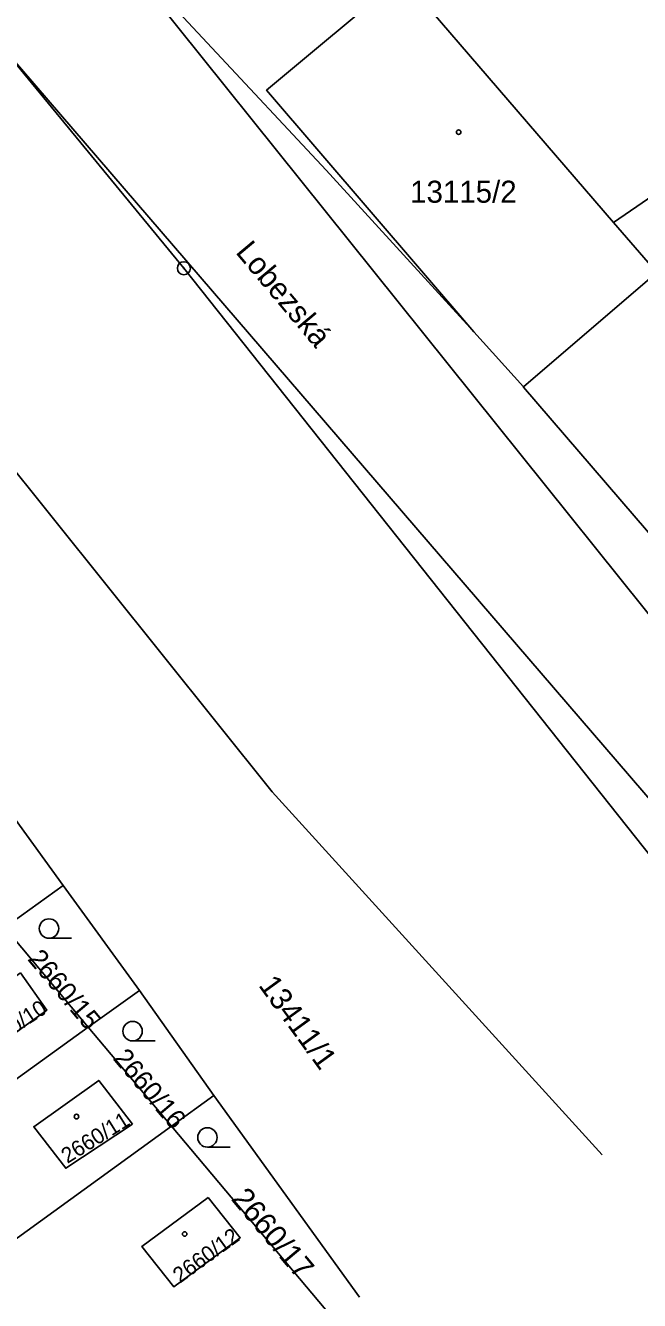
# Model space of a CAD drawing. Extents: x -821458 to -820266, y -1071458 to -1069826.
# Drawn here: x -820545.4 to -820498, y -1071392.4 to -1071294.1 of the extents above; entities that cross this region are included whole.
import ezdxf

# ---------------------------------------------------------------- set-up
doc = ezdxf.new("R2010")
doc.units = 0
for name, color, linetype in [('Vrstva 1', 7, 'Continuous'), ('Vrstva 2', 7, 'Continuous'), ('Vrstva 3', 7, 'Continuous'), ('Vrstva 4', 7, 'Continuous'), ('Vrstva 5', 7, 'Continuous'), ('Vrstva 6', 7, 'Continuous'), ('Vrstva 7', 7, 'Continuous'), ('Vrstva 8', 7, 'Continuous')]:
    doc.layers.add(name, color=color, linetype=linetype)

msp = doc.modelspace()

# ---------------------------------------------------------------- linework, layer by layer
at = {"layer": 'Vrstva 1'}
for p, q in [((-820506.98, -1071321.94), (-820510.8, -1071317.69)), ((-820542.47, -1071360.42), (-820554.5, -1071343.84)), ((-820546.99, -1071363.66), (-820542.47, -1071360.42)), ((-820542.47, -1071360.42), (-820536.6, -1071368.5)), ((-820540.54, -1071371.34), (-820546.99, -1071363.66)), ((-820540.54, -1071371.34), (-820536.6, -1071368.5)), ((-820536.6, -1071368.5), (-820530.86, -1071376.6)), ((-820557.71, -1071383.7), (-820540.54, -1071371.34)), ((-820534.12, -1071378.97), (-820540.54, -1071371.34)), ((-820534.12, -1071378.97), (-820530.86, -1071376.6)), ((-820534.12, -1071378.97), (-820551.8, -1071391.81))]:
    msp.add_line(p, q, dxfattribs=at)
for points in [[(-820485.86, -1071372.383), (-820533.17, -1071312.78), (-820547.67, -1071295.15), (-820551.62, -1071291.15), (-820556.95, -1071290.24), (-820564.58, -1071281.57)], [(-820510.8, -1071317.69), (-820522.19, -1071305.22), (-820540.54, -1071285.54)], [(-820510.8, -1071317.69), (-820526.79, -1071299.05), (-820516.32, -1071290.31), (-820500.02, -1071309.25)], [(-820452.69, -1071340.19), (-820488.09, -1071301.05), (-820500.02, -1071309.25)], [(-820500.02, -1071309.25), (-820496.69, -1071313.12), (-820506.98, -1071321.94)], [(-820506.98, -1071321.94), (-820506.97, -1071321.95), (-820476, -1071357.98), (-820472.55, -1071360.07), (-820469.1, -1071360.69), (-820464.99, -1071360.03), (-820463.371, -1071359.2)], [(-820545.77, -1071367.15), (-820543.74, -1071370.03), (-820548.64, -1071373.54), (-820550.69, -1071370.64), (-820545.77, -1071367.15)], [(-820537.14, -1071378.82), (-820542.28, -1071382.23), (-820544.75, -1071379.02), (-820539.74, -1071375.45), (-820537.14, -1071378.82)], [(-820530.86, -1071376.6), (-820519.616, -1071392.17)], [(-820521.802, -1071393.452), (-820522.21, -1071393.16), (-820534.12, -1071378.97)], [(-820531.29, -1071384.48), (-820528.82, -1071387.59), (-820533.93, -1071391.38), (-820536.4, -1071388.26), (-820531.29, -1071384.48)]]:
    msp.add_lwpolyline(points, dxfattribs=at)
at = {"layer": 'Vrstva 3'}
for p, q in [((-820543.573, -1071364.48), (-820541.823, -1071364.48)), ((-820537.123, -1071372.4), (-820535.373, -1071372.4)), ((-820531.353, -1071380.6), (-820529.603, -1071380.6))]:
    msp.add_line(p, q, dxfattribs=at)
for centre in [(-820543.573, -1071363.73), (-820537.123, -1071371.65), (-820531.353, -1071379.85)]:
    msp.add_circle(centre, 0.75, dxfattribs=at)
at = {"layer": 'Vrstva 4'}
for p, q in [((-820540.54, -1071285.54), (-820479.66, -1071361.53)), ((-820486.8, -1071365.91), (-820547.67, -1071295.15))]:
    msp.add_line(p, q, dxfattribs=at)
at = {"layer": 'Vrstva 5'}
for centre in [(-820511.977, -1071302.279), (-820541.447, -1071378.239), (-820533.107, -1071387.299)]:
    msp.add_circle(centre, 0.175, dxfattribs=at)
at = {"layer": 'Vrstva 6'}
for p, q in [((-820526.35, -1071353.17), (-820561.35, -1071309.57)), ((-820500.902, -1071381.2), (-820526.35, -1071353.17))]:
    msp.add_line(p, q, dxfattribs=at)
at = {"layer": 'Vrstva 8'}
for radius in [0.5, 0.0303]:
    msp.add_circle((-820533.17, -1071312.78), radius, dxfattribs=at)

# ---------------------------------------------------------------- texts
at = {"layer": 'Vrstva 2'}
msp.add_text('13115/2', height=1.7, dxfattribs=at).set_placement((-820515.718, -1071307.729))
for s, height, rotation, p in [('2660/15', 1.5, 310, (-820545.281, -1071366.117)), ('13411/1', 1.7, 306, (-820527.463, -1071368.114)), ('2660/10', 1.2, 33, (-820548.493, -1071373.333)), ('2660/16', 1.5, 310, (-820538.691, -1071373.777)), ('2660/11', 1.2, 32, (-820542.152, -1071381.898)), ('2660/17', 1.7, 310, (-820529.578, -1071384.626)), ('2660/12', 1.2, 36, (-820533.467, -1071391.135))]:
    msp.add_text(s, height=height, rotation=rotation, dxfattribs=at).set_placement(p)
at = {"layer": 'Vrstva 7'}
msp.add_text('Lobezská', height=1.7, rotation=310, dxfattribs=at).set_placement((-820529.238, -1071311.567))

doc.saveas('drawing.dxf')
